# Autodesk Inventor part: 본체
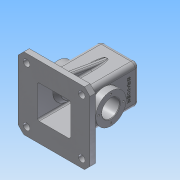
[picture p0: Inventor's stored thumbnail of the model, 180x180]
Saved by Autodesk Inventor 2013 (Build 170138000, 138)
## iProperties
Created: 2016-02
Part Number: 본체
Material: 알루미늄 6061
Document SubType Name: Modeling
Designer: Administrator
Density: 2.71 g/cm^3
Mass: 938.853 g
Surface Area: 1044.45 cm^2
Volume: 346.44 cm^3
Author: Administrator
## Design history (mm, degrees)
sketch "스케치1"
  geometry: L1 (-35, 65)-(35, 65); L2 (35, 65)-(35, -55); L3 (35, -55)-(-35, -55); L4 (-35, -55)-(-35, 65); 2 further points
  constraints: 8 end point, 2 parallel, 1 horizontal, 1 midpoint, 1 perpendicular, 1 vertical alignment
  dimensions: "d0" = 70 distance of L2.end L3.end; "d1" = 120 distance of L1.end L2.end; "d2" = 55 distance from line of L3 point (0, 0)
extrude "돌출1" new body sketch "스케치1" stored distance "d3" = 70; taper "d4" = 0 deg
feature "쉘1" dims "d5" = 5
sketch "스케치2"
  geometry: L1 (70, 0)-(70, -70) reference; L2 (0, 0)-(70, 0) reference; L3 (0, 0)-(0, -70) reference; L4 (70, -70)-(0, -70) reference; L5 (-30, 30)-(100, 30); L6 (100, 30)-(100, -100); L7 (100, -100)-(-30, -100); L8 (-30, -100)-(-30, 30); L9 (-30, 30)-(100, -100); L10 (100, 30)-(-30, -100); 1 further point
  constraints: 12 end point, 2 midpoint, 2 parallel, 1 horizontal, 1 perpendicular
  dimensions: "d6" = 130 distance of L6.end L7.end; "d7" = 130 distance of L5.end L6.end
extrude "돌출2" join sketch "스케치2" distance "d8" = 10; taper "d9" = 0 deg
chamfer "모따기1" distance "d10" = 10; stored, may be unused: second distance "d11" = 2, angle "d12" = 45 deg
fillet "모깎기1" dims "d13" = 8
fillet "모깎기2" dims "d14" = 8
fillet "모깎기3" dims "d15" = 3
fillet "모깎기4" dims "d16" = 3
node "작업 평면1"
sketch "스케치3"
  geometry: C1 r 20 at (-55, 65); 1 further point
  constraints: 1 centre point, 1 coincident
  dimensions: "d18" = 40 diameter of C1
extrude "돌출3" join sketch "스케치3" stored distance "d19" = 10; taper "d20" = 10 deg
sketch "스케치4"
  geometry: C1 r 27.5 at (27, 45); 1 further point
  constraints: 1 centre point, 1 coincident
  dimensions: "d21" = 55 diameter of C1
extrude "돌출4" join sketch "스케치4" distance "d22" = 13; taper "d23" = 0 deg
sketch "스케치5"
  geometry: C1 r 27.5 at (27, 55) reference; C2 r 27.5 at (27, 55); A1 r 27.5 centre (27, 55) between (0, 60.22) and (0, 49.78) reference; A2 r 27.5 centre (27, 55) between (54, 60.22) and (0, 60.22) reference; A3 r 27.5 centre (27, 55) between (54, 49.78) and (54, 60.22) reference; A4 r 27.5 centre (27, 55) between (0, 49.78) and (54, 49.78) reference; 1 further point
  constraints: 1 centre point, 1 coincident
  dimensions: "d24" = 55 diameter of C2
extrude "돌출5" join sketch "스케치5" distance "d25" = 7; taper "d26" = -45 deg
hole "구멍1" diameter "d29" = 32; stored, may be unused: countersink angle "d33" = 90 deg, drill point angle "d35" = 118 deg; dims "d27" = 10, "d28" = 10, "d30" = 6, "d31" = 4, "d32" = 2, "d34" = 8
hole "구멍2" diameter "d38" = 21; stored, may be unused: countersink angle "d42" = 90 deg, drill point angle "d44" = 118 deg; dims "d36" = 10, "d37" = 10, "d39" = 6, "d40" = 28, "d41" = 4, "d43" = 8
chamfer "모따기2" distance "d45" = 1; stored, may be unused: second distance "d46" = 2, angle "d47" = 45 deg
sketch "스케치6"
  geometry: L1 (-45, 35)-(57, 35) reference; L2 (-45, -55)-(-45, 55) reference; L3 (-45, 65)-(-45, 55) reference; L4 (40.069, 35)-(-45, 50); L5 (-55, 65)-(-45, 65) reference; 1 further point
  constraints: 2 end point, 2 point on line
  dimensions: "d48" = 10 deg angle of L4 L5; "d49" = 15 distance from line of L4.end L5
feature "리브1" sketch "스케치6" dims "d50" = 1, "d51" = 10, "d52" = 0, "d53" = 0, "d54" = 1, "d55" = 1
fillet "모깎기5" dims "d56" = 3
fillet "모깎기6" dims "d57" = 3
fillet "모깎기7" dims "d58" = 3
fillet "모깎기8" dims "d59" = 0.5
sketch "스케치7"
  geometry: C1 r 27.5 at (0, 0) reference; 1 further point
  constraints: 1 vertical alignment
  dimensions: "d60" = 22.5 distance of C1.centre point (0, 22.5)
hole "구멍3" sketch "스케치7" at (0, 22.5) diameter "d61" = 3.242; stored, may be unused: countersink angle "d65" = 90 deg, drill point angle "d67" = 118 deg; dims "d62" = 8, "d63" = 3, "d64" = 4, "d66" = 10
sketch "스케치8"
  geometry: L1 (7, 18)-(47, 18) reference; L2 (62, -99)-(62, 0) reference; 1 further point
  constraints: 1 other
  dimensions: "d71" = 30 distance from line of point (27, -12) L1; "d72" = 35 distance from line of point (27, -12) L2
feature "엠보싱1" sketch "스케치8" dims "d6" = 130, "d7" = 130, "d73" = 0.5, "d74" = 0
sketch "스케치9"
  geometry: L1 (0, 0)-(110, 0) reference; L2 (-10, -120)-(-10, -10) reference; C1 r 6 at (5, -15); C2 r 6 at (105, -15); 1 further point
  constraints: 2 centre point, 1 horizontal alignment
  dimensions: "d75" = 12 diameter of C1; "d76" = 15 distance from line of C1.centre L2; "d77" = 15 distance from line of C1.centre L1; "d78" = 12 diameter of C2; "d79" = 100 distance of C2.centre C1.centre
extrude "돌출6" cut sketch "스케치9" stored distance "d81" = 7; taper "d82" = 0 deg
fillet "모깎기9" dims "d83" = 3
fillet "모깎기10" dims "d84" = 0.5
node "솔리드1"
mirror "대칭1"
mirror "대칭2"
pattern_circular "원형 패턴1" dims angle "d69" = 360 deg
mirror "대칭3"
mirror "대칭4"
node "투영된 루프1"
